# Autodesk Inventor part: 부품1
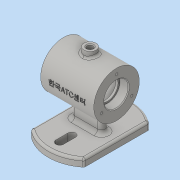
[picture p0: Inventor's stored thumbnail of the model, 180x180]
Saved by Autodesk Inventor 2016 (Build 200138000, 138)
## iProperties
Created: 2017-12
Part Number: 부품1
Material: 일반
Document SubType Name: Modeling
Designer: 605-07
Density: 1 g/cm^3
Appearance: 기본값
Author: 605-07
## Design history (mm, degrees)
sketch "스케치1"
  geometry: L1 (35, 0)-(-35, 0); L2 (35, 30)-(-35, 30); L3 (-35, 30)-(-35, 16); L4 (-35, 16)-(-23, 16); L5 (-23, 16)-(-23, 14); L6 (-23, 14)-(-20, 14); L7 (-20, 14)-(-20, 25); L8 (-20, 25)-(20, 25); L9 (20, 25)-(20, 14); L10 (20, 14)-(23, 14); L11 (23, 14)-(23, 16); L12 (23, 16)-(35, 16); L13 (35, 16)-(35, 30); 1 further point
  constraints: 26 end point, 8 perpendicular, 3 horizontal, 1 midpoint, 1 vertical, 1 vertical alignment
  dimensions: "d1" = 35 distance of L1.start point (0, 0); "d2" = 70 distance of L1.start L1.end; "d3" = 70 distance of L2.start L2.end; "d4" = 12 distance of L3.end L4.end; "d5" = 3 distance of L5.end L6.end; "d7" = 40 distance of L7.end L8.end; "d8" = 3 distance of L9.end L10.end; "d9" = 12 distance of L11.end L12.end; "d10" = 60 diameter of L2 L1; "d11" = 50 diameter of L8 L1; "d12" = 32 diameter of L12 L1; "d13" = 28 diameter of L10 L1; "d14" = 32 diameter of L4 L1; "d15" = 28 diameter of L6 L1
revolve "회전1" sketch "스케치1" stored, may be unused: angle "d16" = 90 deg
node "작업 평면2"
sketch "스케치3"
  geometry: L1 (-35, -42.426)-(35, -42.426); L2 (35, -42.426)-(35, 42.426); L3 (35, 42.426)-(-35, 42.426); L4 (-35, 42.426)-(-35, -42.426); L5 (-35, -42.426)-(35, 42.426); L6 (35, -42.426)-(-35, 42.426); A1 r 55 centre (0, 0) between (-35, -42.426) and (35, -42.426); A2 r 55 centre (0, 0) between (35, 42.426) and (-35, 42.426); 1 further point
  constraints: 12 end point, 4 point on circle, 2 centre point, 2 midpoint, 2 parallel, 1 coincident, 1 horizontal, 1 perpendicular
  dimensions: "d27" = 70 distance of L2.end L3.end; "d28" = 55 radius of A2
extrude "돌출1" join sketch "스케치3" distance "d29" = 10; taper "d30" = 0 deg
sketch "스케치4"
  geometry: L1 (-15, 0)-(15, 0); L2 (-15, -5)-(15, -5); L3 (15, 5)-(-15, 5); A1 r 5 centre (-15, 0) between (-15, 5) and (-15, -5); A2 r 5 centre (15, 0) between (15, -5) and (15, 5); 2 further points
  constraints: 8 end point, 4 point on circle, 4 tangent, 2 centre point, 1 coincident, 1 horizontal, 1 midpoint, 1 parallel
  dimensions: "d31" = 5 radius of A2; "d32" = 30 distance of L3.start L3.end
extrude "돌출2" join sketch "스케치4" stored distance "d33" = 10; taper "d34" = 0 deg; dims "d27" = 70, "d28" = 55
node "작업 평면3"
sketch "스케치5"
  geometry: C1 r 8 at (0, 0); 1 further point
  constraints: 1 centre point, 1 coincident
  dimensions: "d36" = 16 diameter of C1
extrude "돌출3" join sketch "스케치5" stored distance "d37" = 10; taper "d38" = 0 deg; dims "d27" = 70, "d28" = 55
node "작업 평면4"
sketch "스케치6"
  geometry: L1 (-35, 30)-(-35, -30) reference; L2 (35, 30)-(-35, 30) reference; 2 further points
  constraints: 1 other
  dimensions: "d39" = 35 distance from line of L1 point (0, 0); "d40" = 30 distance from line of L2 point (0, 0)
feature "엠보싱1" sketch "스케치6" dims "d1" = 35, "d2" = 70, "d3" = 70, "d4" = 12, "d5" = 3, "d7" = 40, "d8" = 3, "d9" = 12, "d10" = 60, "d11" = 50, "d12" = 32, "d13" = 28, "d14" = 32, "d15" = 28, "d27" = 70, "d28" = 55, "d41" = 0.5, "d42" = 0
fillet "모깎기1" dims "d43" = 3
fillet "모깎기2" dims "d44" = 3
fillet "모깎기3" dims "d45" = 3
sketch "스케치7"
  geometry: L1 (0, 40)-(0, 24); L2 (-5, 40)-(-5, 24); L3 (5, 24)-(5, 40); A1 r 5 centre (0, 40) between (5, 40) and (-5, 40); A2 r 5 centre (0, 24) between (-5, 24) and (5, 24); 2 further points
  constraints: 8 end point, 4 point on circle, 4 tangent, 2 centre point, 1 midpoint, 1 parallel, 1 vertical, 1 vertical alignment
  dimensions: "d46" = 5 radius of A1; "d47" = 16 distance of L3.start L3.end; "d48" = 32 distance of point (0, 0) point (0, 32)
extrude "돌출4" cut sketch "스케치7" stored distance "d49" = 10; taper "d50" = 0 deg
sketch "스케치8" dims "d51" = 46
  geometry: 3 further points
  constraints: 2 horizontal alignment, 1 coincident, 2 other
hole "구멍1" sketch "스케치8" at (-23, 0) diameter "d52" = 3.242; stored, may be unused: countersink angle "d56" = 90 deg, drill point angle "d58" = 120 deg; dims "d53" = 8, "d54" = 4, "d55" = 2, "d57" = 10
hole "구멍2" diameter "d64" = 8; stored, may be unused: countersink angle "d68" = 90 deg, drill point angle "d70" = 0 deg; dims "d62" = 10, "d63" = 10, "d65" = 8, "d66" = 4, "d67" = 2, "d69" = 15.25
chamfer "모따기1" distance "d71" = 1; stored, may be unused: second distance "d72" = 2, angle "d73" = 45 deg
fillet "모깎기4" dims "d74" = 3
fillet "모깎기5" dims "d75" = 0.3
fillet "모깎기6" dims "d76" = 5
node "솔리드1"
mirror "대칭1"
pattern_circular "원형 패턴1" dims angle "d60" = 360 deg
mirror "대칭2"
other parameters: "d23" = -62, "d35" = 37
